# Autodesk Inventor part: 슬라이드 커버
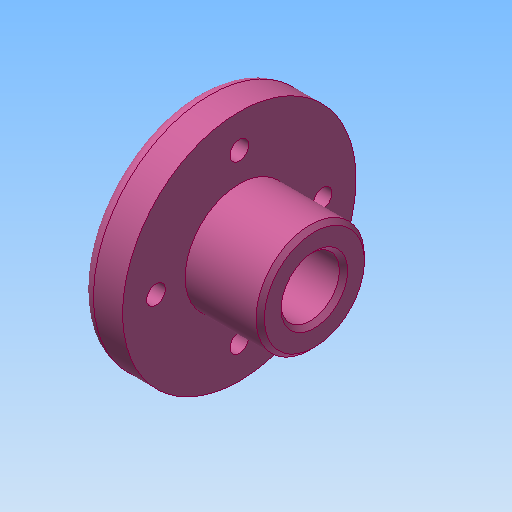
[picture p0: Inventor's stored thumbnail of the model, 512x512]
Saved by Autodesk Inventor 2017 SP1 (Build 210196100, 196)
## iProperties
Created: 2015-12
Part Number: 슬라이드 커버
Document SubType Name: Modeling
Designer: mdu
Density: 2.71 g/cm^3
Material: 알루미늄 6061
Mass: 76.471 g
Surface Area: 93.8237 cm^2
Volume: 28.2181 cm^3
Appearance: 분홍색
Author: mdu
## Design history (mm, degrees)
sketch "스케치1"
  geometry: L1 (-14, 0)-(14, 0); L2 (-14, 0)-(-14, 28); L3 (-14, 28)-(-4, 28); L4 (-4, 28)-(-4, 13); L5 (-4, 13)-(14, 13); L6 (14, 13)-(14, 0); 2 further points
  constraints: 12 end point, 3 perpendicular, 1 coincident, 1 horizontal, 1 midpoint, 1 parallel
  dimensions: "d1" = 56 diameter of L3 L1; "d2" = 26 diameter of L5 L1; "d5" = 10 distance of L2.end L3.end; "d32" = 18 distance of L4.end L5.end
revolve "회전1" sketch "스케치1" stored, may be unused: angle "d6" = 90 deg
sketch "스케치2" dims "d33" = 40
  geometry: 3 further points
  constraints: 2 vertical alignment, 1 coincident, 2 other
hole "구멍1" sketch "스케치2" at (0, 20) diameter "d8" = 4.5; stored, may be unused: countersink angle "d12" = 90 deg, drill point angle "d14" = 118 deg; dims "d9" = 6, "d10" = 8, "d11" = 4.4, "d13" = 8
hole "구멍2" diameter "d20" = 14; stored, may be unused: countersink angle "d24" = 90 deg, drill point angle "d26" = 0 deg; dims "d18" = 10, "d19" = 10, "d21" = 6, "d22" = 8, "d23" = 4.4, "d25" = 8
fillet "모깎기1" dims "d27" = 3
chamfer "모따기1" distance "d29" = 1; stored, may be unused: second distance "d30" = 2, angle "d31" = 45 deg
node "솔리드1"
pattern_circular "원형 패턴1" dims angle "d16" = 360 deg
